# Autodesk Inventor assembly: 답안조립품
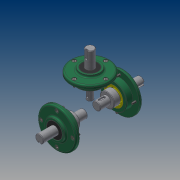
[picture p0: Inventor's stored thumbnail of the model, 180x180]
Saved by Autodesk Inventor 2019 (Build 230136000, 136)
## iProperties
Created: 2019-03
Part Number: 답안조립품
Material: 일반
Document SubType Name: Assembly
Designer: PC312-03
Author: PC312-03
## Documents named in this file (12)
- C:\Users\PC312-03\Desktop\490314V1011\답안조립품.iam
- C:\Users\PC312-03\Desktop\490314V1011\본체.ipt
- C:\Users\PC312-03\Desktop\490314V1011\커버.ipt
- C:\Users\PC312-03\Desktop\490314V1011\볼트 M4.ipt
- 볼트 M4.ipt
- C:\Users\PC312-03\Desktop\490314V1011\오일 실.ipt
- 오일 실.ipt
- C:\Users\PC312-03\Desktop\490314V1011\베어링 6203.ipt
- C:\Users\PC312-03\Desktop\490314V1011\메인 축.ipt
- 메인 축.ipt
- C:\Users\PC312-03\Desktop\490314V1011\서브 축.ipt
- 서브 축.ipt
